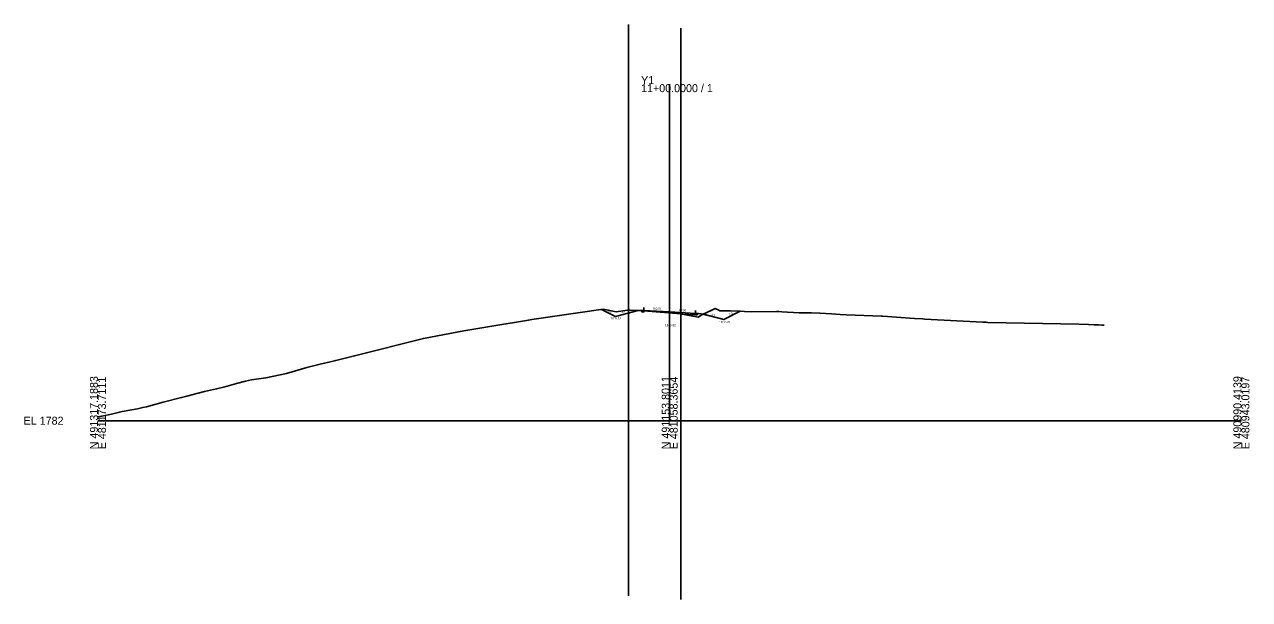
# Model space of a CAD drawing. Extents: x -26 to 403, y -10 to 6561.
# Drawn here: x -25.7 to 402.8, y 937.4 to 1138.7 of the extents above; entities that cross this region are included whole.
import ezdxf

# ---------------------------------------------------------------- set-up
doc = ezdxf.new("R2010")
doc.units = 0
for name, color, linetype in [('Exist Cross Section Cell', 7, 'Continuous'), ('Exist XS Center Line Elevation Label', 7, 'Continuous'), ('Exist XS Ground Line', 7, 'Continuous'), ('Prop Road Sect_ Boring - Header (ID Tx)', 7, 'Continuous'), ('Prop Road Sect_ Material - Tx (Composite Desc)', 7, 'Continuous'), ('Prop XS Ditch Slope Text', 7, 'Continuous'), ('Prop XS Ditch Standard Text', 7, 'Continuous'), ('Prop XS EOT Tick Mark', 7, 'Continuous'), ('Prop XS Finish Grade', 7, 'Continuous'), ('Prop XS Finish Grade Earthwork', 7, 'Continuous'), ('Prop XS Finish Grade Pavement', 7, 'Continuous'), ('Prop XS Pvmt Edge Slope', 7, 'Continuous'), ('Prop XS SE Text', 7, 'Continuous'), ('Prop XS Side Slope Text', 7, 'Continuous'), ('Prop XS Subgrade Earthwork', 7, 'Continuous'), ('Scratch_Level_1', 7, 'Continuous'), ('Scratch_Level_4', 7, 'Continuous')]:
    doc.layers.add(name, color=color, linetype=linetype)

msp = doc.modelspace()

# ---------------------------------------------------------------- linework, layer by layer
at = {"layer": 'Exist Cross Section Cell'}
for p, q in [((200, 1000), (200, 1117.8)), ((0, 1000), (200, 1000)), ((200, 1000), (400, 1000))]:
    msp.add_line(p, q, dxfattribs=at)
at = {"layer": 'Exist XS Ground Line'}
msp.add_lwpolyline([(0, 1001.35), (1.33, 1001.64), (4.77, 1002.35), (8.51, 1003.21), (13.81, 1004.21), (15.69, 1004.64), (17.01, 1004.91), (22.86, 1006.49), (29.26, 1008.12), (31.15, 1008.63), (37.22, 1010.21), (41.5, 1011.15), (44.39, 1011.85), (48.49, 1013.04), (51.57, 1013.9), (53.74, 1014.28), (58.75, 1015.05), (65.99, 1016.55), (73.1, 1018.62), (78.23, 1019.94), (80.28, 1020.39), (83.18, 1021.11), (89.77, 1022.66), (113.88, 1028.81), (128.02, 1031.42), (142.7, 1033.9), (145.03, 1034.3), (150.57, 1035.23), (151.79, 1035.41), (176.72, 1039.01), (180.13, 1038.32), (181.23, 1038.15), (185.22, 1038.65), (185.59, 1038.69), (186.19, 1038.66), (190.84, 1038.49), (194.39, 1038.35), (194.81, 1038.35), (197.23, 1038.1), (200, 1037.82), (203.99, 1037.41), (206.8, 1036.86), (208.79, 1036.48), (209.94, 1036.25), (211.28, 1037.01), (215.89, 1039.27), (217.18, 1038.7), (217.53, 1038.41), (221.28, 1038.46), (228.65, 1038.1), (237.39, 1038.23), (238.17, 1038.19), (239.26, 1038.13), (245.34, 1037.76), (249.64, 1037.72), (252.52, 1037.61), (256.6, 1037.42), (259.7, 1037.2), (261.88, 1037.07), (274.12, 1036.56), (274.54, 1036.54), (285.7, 1035.76), (288.48, 1035.63), (289.3, 1035.57), (309.45, 1034.47), (310.69, 1034.48), (311.32, 1034.38), (343.13, 1033.79), (346.5, 1033.7), (348.5, 1033.6), (349.99, 1033.51), (351.13, 1033.5), (352.04, 1033.48)], dxfattribs=at)
at = {"layer": 'Prop Road Sect_ Boring - Header (ID Tx)'}
for points in [[(191, 1038.6), (189.95, 1038.56), (190.45, 1038.05)], [(209, 1037.58), (209.58, 1037.01), (210.09, 1037.52)]]:
    msp.add_lwpolyline(points, close=True, dxfattribs=at)
at = {"layer": 'Prop Road Sect_ Material - Tx (Composite Desc)'}
for points in [[(181, 1036.52), (176.18, 1038.93), (176.72, 1039.01), (180.13, 1038.32), (181.23, 1038.15), (185.22, 1038.65), (185.59, 1038.69), (186.19, 1038.66), (189.48, 1038.54), (189, 1038.52)], [(189.48, 1038.54), (189.99, 1038.52), (189.95, 1038.56)], [(189.99, 1038.52), (190.84, 1038.49), (191, 1038.48), (191, 1038.06), (190.45, 1038.05)], [(204.5, 1037.31), (203.96, 1037.35), (203.96, 1037.42), (203.99, 1037.41)], [(204.5, 1037.31), (206.8, 1036.86), (208.79, 1036.48), (209.94, 1036.25), (211.28, 1037.01), (211.8, 1037.27), (211, 1037.46), (210.09, 1037.52), (209.58, 1037.01), (209, 1037.04)], [(219, 1035.46), (224.66, 1038.29), (221.28, 1038.46), (217.53, 1038.41), (217.18, 1038.7), (215.89, 1039.27), (211.8, 1037.27)]]:
    msp.add_lwpolyline(points, close=True, dxfattribs=at)
at = {"layer": 'Prop XS EOT Tick Mark'}
for p, q in [((191, 1038.6), (191, 1039.6)), ((209, 1037.58), (209, 1038.58))]:
    msp.add_line(p, q, dxfattribs=at)
at = {"layer": 'Prop XS Finish Grade'}
for p, q in [((191, 1038.6), (189.95, 1038.56)), ((209, 1037.58), (210.09, 1037.52))]:
    msp.add_line(p, q, dxfattribs=at)
at = {"layer": 'Prop XS Finish Grade Earthwork'}
for p, q in [((181, 1036.52), (176.18, 1038.93)), ((189, 1038.52), (181, 1036.52)), ((189, 1038.52), (189.95, 1038.56)), ((210.09, 1037.52), (211, 1037.46)), ((211, 1037.46), (219, 1035.46)), ((219, 1035.46), (224.66, 1038.29))]:
    msp.add_line(p, q, dxfattribs=at)
at = {"layer": 'Prop XS Finish Grade Pavement'}
for p, q in [((191, 1038.6), (200, 1038.12)), ((200, 1038.12), (209, 1037.58))]:
    msp.add_line(p, q, dxfattribs=at)
at = {"layer": 'Prop XS Pvmt Edge Slope'}
for p, q in [((191, 1038.6), (190.45, 1038.05)), ((209, 1037.58), (209.58, 1037.01))]:
    msp.add_line(p, q, dxfattribs=at)
at = {"layer": 'Prop XS Subgrade Earthwork'}
for p, q in [((190.45, 1038.05), (189.95, 1038.56)), ((191, 1038.06), (190.45, 1038.05)), ((191, 1038.48), (191, 1038.06)), ((203.96, 1037.35), (203.96, 1037.42)), ((209, 1037.04), (203.96, 1037.35)), ((209.58, 1037.01), (210.09, 1037.52)), ((209, 1037.04), (209.58, 1037.01))]:
    msp.add_line(p, q, dxfattribs=at)
at = {"layer": 'Scratch_Level_1'}
for p, q in [((185.56, 1138.69), (185.56, 938.69)), ((203.96, 1137.42), (203.96, 937.42))]:
    msp.add_line(p, q, dxfattribs=at)
at = {"layer": 'Scratch_Level_4'}
msp.add_line((191, 1038.48), (203.96, 1037.42), dxfattribs=at)

# ---------------------------------------------------------------- texts
at = {"layer": 'Exist Cross Section Cell'}
for s, p in [('Y1', (190, 1117.8)), ('11+00.0000 / 1', (190, 1115)), ('EL 1782', (-26, 998.6))]:
    msp.add_text(s, height=2.8, dxfattribs=at).set_placement(p)
for s, p in [('N 491317.1883', (0, 990)), ('E 481173.7111', (2.8, 990)), ('N 491153.8011', (200, 990)), ('E 481058.3654', (202.8, 990)), ('N 490990.4139', (400, 990)), ('E 480943.0197', (402.8, 990))]:
    msp.add_text(s, height=2.8, rotation=90, dxfattribs=at).set_placement(p)
at = {"layer": 'Exist XS Center Line Elevation Label'}
msp.add_text('1819.82', height=0.75, dxfattribs=at).set_placement((198.39, 1033.07))
at = {"layer": 'Prop XS Ditch Slope Text'}
for rotation, p in [(14.0362, (183.28, 1037.56)), (345.9638, (214.43, 1036.82))]:
    msp.add_text('4:1', height=0.75, rotation=rotation, dxfattribs=at).set_placement(p)
at = {"layer": 'Prop XS Ditch Standard Text'}
for s, p in [('1818.52', (179.31, 1035.45)), ('1817.46', (217.31, 1034.15))]:
    msp.add_text(s, height=0.75, dxfattribs=at).set_placement(p)
at = {"layer": 'Prop XS SE Text'}
for s, rotation, p in [('0.053', 356.9852, (194.21, 1038.93)), ('0.060', 356.5664, (203.19, 1038.43))]:
    msp.add_text(s, height=0.75, rotation=rotation, dxfattribs=at).set_placement(p)
at = {"layer": 'Prop XS Side Slope Text'}
for rotation, p in [(333.4349, (178.26, 1038.43)), (26.5651, (220.9, 1036.78))]:
    msp.add_text('2:1', height=0.75, rotation=rotation, dxfattribs=at).set_placement(p)

doc.saveas('drawing.dxf')
